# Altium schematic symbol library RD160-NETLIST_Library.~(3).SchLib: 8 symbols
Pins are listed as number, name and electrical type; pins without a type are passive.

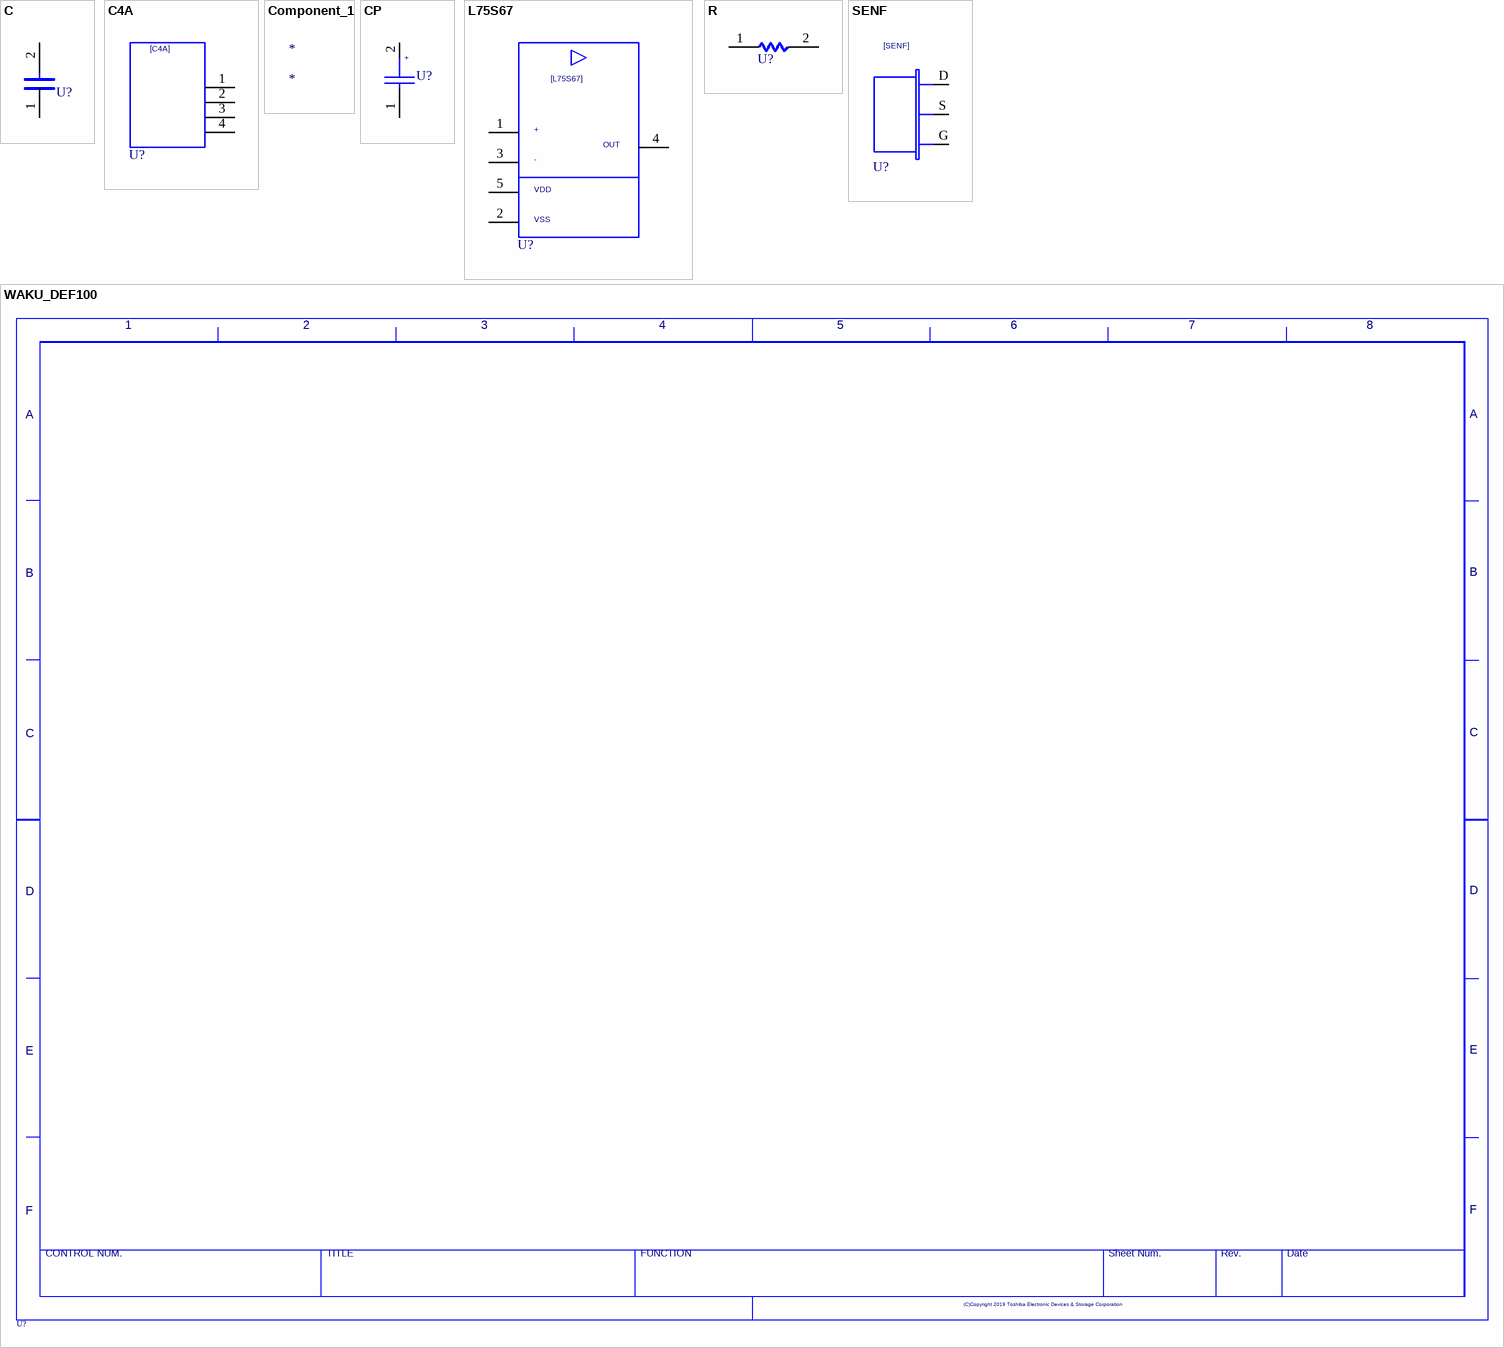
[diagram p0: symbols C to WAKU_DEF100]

## C
designator U?  (value not drawn)
OriginalSymbolOrigin: (2540,7620); Altium-Right: 20; Altium-Bottom: 10
pins: 1, 2

## C4A
designator U?  (value not drawn)
SAVEAREA0: -8845,-265,28754,23475; SAVECOUNT: 22; TIME: 13:28:28; UPDATEUSER: tomizawa-y; UPDATETIME: 15:03:27; OriginalSymbolOrigin: (2540,20320); Altium-Right: 50; Altium-Bottom: 70
pins: 1, 2, 3, 4

## Component_1
designator *

## CP
designator U?  (value not drawn)
SAVEAREA0: -1450,-153,20294,13055; SAVECOUNT: 52; TIME: 15:02:55; UPDATEUSER: fukuda-y; UPDATETIME: 16:13:42; OriginalSymbolOrigin: (2540,10160); Altium-Right: 20
pins: 1, 2

## L75S67
designator U?  (value not drawn)
TIME: 16:27:13; UPDATEUSER: w90028dm; UPDATETIME: 15:17:13; SAVECOUNT: 13; SAVEAREA0: -43421,-10273,73920,48138; OriginalSymbolOrigin: (5080,35560); Altium-Right: 80; Altium-Bottom: 130
pins: 1, 2, 3, 4, 5

## R
designator U?  (value not drawn)
OriginalSymbolOrigin: (5080,5080); Altium-Right: 20
pins: 1, 2

## SENF
designator U?  (value not drawn)
TIME: 14:34:58; UPDATEUSER: w90028dm; UPDATETIME: 13:22:07; SAVECOUNT: 25; SAVEAREA0: -45006,-15118,60589,37447; OriginalSymbolOrigin: (2540,17780); Altium-Right: 40; Altium-Bottom: 60
pins: D, G, S

## WAKU_DEF100
designator U?  (value not drawn)
PLOTTIME: HH:MM; SAVEAREA0: 198008,-65938,436964,90161; TIME: 14:30:25; UPDATEUSER: d5009410; UPDATETIME: 15:37:05; SAVECOUNT: 4; OriginalSymbolOrigin: (10160,284480); Altium-Right: 1570; Altium-Bottom: 1070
